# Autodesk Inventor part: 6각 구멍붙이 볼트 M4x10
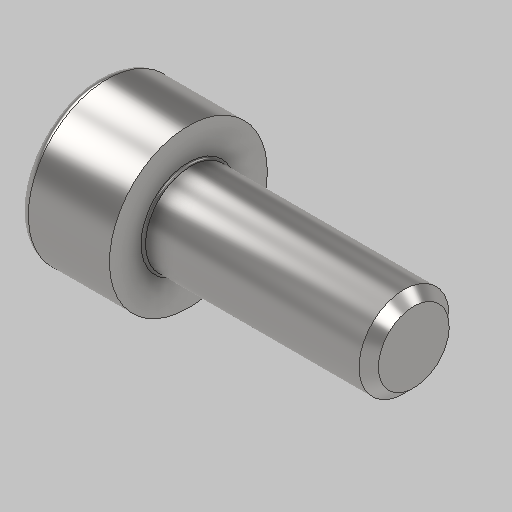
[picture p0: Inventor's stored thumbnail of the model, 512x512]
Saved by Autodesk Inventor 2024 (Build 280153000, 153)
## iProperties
Created: 2026-01
Part Number: 6각 구멍붙이 볼트 M4x10
Material: 강철, 연강
Description: 6각머리 태핑 나사
Document SubType Name: Modeling
Designer: 2-10
Density: 7.85 g/cm^3
Appearance: 기본값
Author: jhkim
Sending System: Autodesk Inventor 2026
Preprocessor: ST-DEVELOPER v20.1
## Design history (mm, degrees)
feature "Solid1"
node "솔리드1"
